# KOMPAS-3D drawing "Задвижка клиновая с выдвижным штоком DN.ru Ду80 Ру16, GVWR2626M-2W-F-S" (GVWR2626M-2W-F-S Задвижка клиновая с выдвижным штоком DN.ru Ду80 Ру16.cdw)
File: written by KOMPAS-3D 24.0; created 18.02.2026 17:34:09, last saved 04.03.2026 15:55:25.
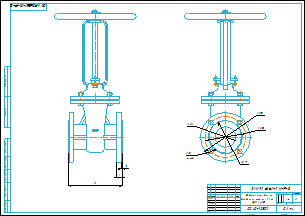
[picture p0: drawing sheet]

Document properties: Автор: R2D2; Форматы листов документа: A2; Полное имя файла: GVWR2626M-2W-F-S Задвижка клиновая с выдвижным штоком DN.ru Ду80 Ру16.m3d; Масса: 24; Наименование: Задвижка клиновая с выдвижным штоком DN.ru Ду80 Ру16; Количество листов документа: 1; Примечание: D040-10501

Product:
- Component [detail]: Деталь2  | qty 1  | pos. 1  | Автор: R2D2; additional columns: Типовые; source file: исходные материалы\Деталь2 Деталь2.m3d
- Component [detail]: AS 1110 - M12 x 45  | qty 4  | pos. 2  | Комментарий: Болты и винты   шестигранные точные   метрические ISO; Автор: R2D2; additional columns: Сталь, мягкая; source file: исходные материалы\AS 1110 - M12 x 45 AS 1110 - M12 x 45.m3d
- Component [detail]: ANSI B18.2.4.2M - M12x1,75 - 18  | designation ANSI B18.2.4.2M - M12x1,75  | qty 4  | pos. 3  | Комментарий: Типы метрических   шестигранных гаек   2; Автор: R2D2; additional columns: Сталь, мягкая; source file: исходные материалы\ANSI B18.2.4.2M - M12x1,75 ANSI B18.2.4.2M - M12x1,75 - 18.m3d
- Component [detail]: ANSI B18.2.4.2M - M5x0,8 - 8  | designation ANSI B18.2.4.2M - M5x0,8  | qty 2  | pos. 4  | Комментарий: Типы метрических   шестигранных гаек   2; Автор: R2D2; additional columns: Сталь, мягкая; source file: исходные материалы\ANSI B18.2.4.2M - M5x0,8 ANSI B18.2.4.2M - M5x0,8 - 8.m3d
- Component [detail]: Деталь1  | qty 1  | pos. 5  | additional columns: Типовые; source file: исходные материалы\2.m3d
- Component [detail]: Деталь1  | qty 1  | pos. 5  | Автор: R2D2; additional columns: Типовые; source file: исходные материалы\3.m3d
- Component [detail]: Фланец  | qty 2  | pos. 5  | Автор: R2D2; additional columns: Типовые; source file: исходные материалы\Фланец DN80 PN16 b20.m3d
- Part/product: Задвижка клиновая с выдвижным штоком DN.ru Ду80 Ру16  | designation GVWR2626M-2W-F-S
    Масса: 24
    Раздел спецификации: Прочие изделия
    Примечание: D040-10501

Referenced files in E:\Работа\Зайцев\Для компаса\: чертеж DN.ru А3.cdt
Referenced files in E:\Работа\Зайцев\GVWR2626M-2W-F-S Задвижка клиновая с выдвижным штоком DN.ru Ду50-300 Ру16\DN80\исходные материалы\: Деталь2 Деталь2.m3d, AS 1110 - M12 x 45 AS 1110 - M12 x 45.m3d, ANSI B18.2.4.2M - M12x1,75 ANSI B18.2.4.2M - M12x1,75 - 18.m3d, ANSI B18.2.4.2M - M5x0,8 ANSI B18.2.4.2M - M5x0,8 - 8.m3d, 2.m3d, 3.m3d, Фланец DN80 PN16 b20.m3d
Referenced files in E:\Работа\Зайцев\GVWR2626M-2W-F-S Задвижка клиновая с выдвижным штоком DN.ru Ду50-300 Ру16\DN80\: GVWR2626M-2W-F-S Задвижка клиновая с выдвижным штоком DN.ru Ду80 Ру16.m3d
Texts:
  чертеж DN.ru А3.cdt
  Задвижка клиновая с
  выдвижным штоком DN.ru
  Ду80 Ру16
  GVWR2626M-2W-F-S
  Твердое тело1
  Деталь2
  Деталь2 Деталь2
  Solid1
  AS 1110 - M12 x 45
  AS 1110 - M12 x 45 AS 1110 - M12 x 45
  ANSI B18.2.4.2M - M12x1,75 - 18
  ANSI B18.2.4.2M - M12x1,75
  ANSI B18.2.4.2M - M12x1,75 ANSI B18.2.4.2M - M12x1,75 - 18
  ANSI B18.2.4.2M - M5x0,8 - 8
  ANSI B18.2.4.2M - M5x0,8
  ANSI B18.2.4.2M - M5x0,8 ANSI B18.2.4.2M - M5x0,8 - 8
  Деталь1
  Деталь1 Деталь1
  Фланец
  Задвижка клиновая с выдвижным штоком DN.ru Ду80 Ру16
  GVWR2626M-2W-F-S Задвижка клиновая с выдвижным штоком DN.ru Ду80 Ру16
Dimensions and other numbers on the sheet: 1:2; 0; 1; 2; 24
